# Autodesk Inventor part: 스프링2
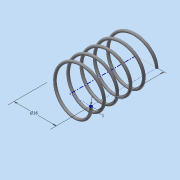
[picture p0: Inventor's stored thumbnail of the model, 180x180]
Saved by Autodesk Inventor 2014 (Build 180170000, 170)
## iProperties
Created: 2015-06
Part Number: 스프링2
Material: 강철, 연강
Document SubType Name: Modeling
Designer: MYHOME
Density: 7.86 g/cm^3
Appearance: 강철
Mass: 1.53535 g
Surface Area: 7.89042 cm^2
Volume: 0.195337 cm^3
Author: MYHOME
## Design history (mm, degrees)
sketch "스케치1"
  geometry: L1 (0, 0)-(8, 0); L2 (8, 0)-(8, 21.5); L3 (8, 21.5)-(0, 21.5); L4 (0, 21.5)-(0, 0); C1 r 0.5 at (8, 0)
  constraints: 8 end point, 2 parallel, 1 centre point, 1 coincident, 1 horizontal, 1 perpendicular
  dimensions: "d0" = 16 diameter of L2 L4; "d1" = 21.5 distance of L1.end L2.end (derived); "d2" = 1 diameter of C1
feature "코일1" sketch "스케치1" pitch "d3" = 10; turns "d5" = 5; dims "d4" = 21.5 (= d1), "d6" = 0, angle "d7" = 90 deg, angle "d8" = 90 deg, "d9" = 0, "d10" = 0
node "작업 평면1"
sketch "스케치2"
  geometry: L1 (-8.5, 0)-(-7.5, 0) reference; 1 further point
  constraints: 1 horizontal alignment
extrude "돌출1" cut sketch "스케치2" stored distance "d12" = 10; taper "d13" = 0 deg
node "작업 평면2"
sketch "스케치3"
  geometry: L1 (8.5, 0)-(7.5, 0) reference; 1 further point
  constraints: 1 horizontal alignment
extrude "돌출2" cut sketch "스케치3" stored distance "d15" = 10; taper "d16" = 0 deg
node "솔리드1"
node "절단 모서리 투영1"
node "절단 모서리 투영2"
other parameters: "d11" = 0, "d14" = -21.5 (= -d1)
